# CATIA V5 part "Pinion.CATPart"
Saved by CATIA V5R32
Part number: Part3
Bounding box of the stored display mesh (mm): x -50 to 70, y -20 to 20, z -20 to 20
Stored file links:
  D:\PROJECTS\Project 2022\CATIA V5 6R 2022\Resources\Part Files\c16_catia_v5_6r2022_prt\Rack Joint(Fig16-57)\Pinion.CATPart
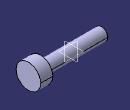
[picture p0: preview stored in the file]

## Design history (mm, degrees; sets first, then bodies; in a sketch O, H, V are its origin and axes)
Body1 (main body)
  Sketch1 on yz-plane, origin (0, 0, 0), H (0, 1, 0), V (0, 0, 1)
    reference intersected line E1 through (0, 0) direction (-1, 0) from xy-plane
    reference intersected line E3 through (0, 0) direction (0, 1) from zx-plane
    reference intersected line E4 through (0, 0) direction (-1, 0) from xy-plane
    reference intersected line E6 through (0, 0) direction (0, 1) from zx-plane
    reference intersected line E7 through (0, 0) direction (-1, 0) from xy-plane
    reference intersected line E9 through (0, 0) direction (0, 1) from zx-plane
    circle A1 centre (0, 0) radius 10
    radius A1 = 10
    vertical: E3 V, E6 V, E9 V
    horizontal: E1 H, E4 H, E7 H
  Pad1: profile Sketch1, direction (1, 0, 0), length 50, mirrored extent
  Sketch2 on end face of Pad1, origin (50, 0, 0), H (0, 1, 0), V (0, 0, 1)
    circle A1 centre (0, 0) radius 20
    radius A1 = 20
  Pad2: profile Sketch2, direction (1, 0, 0), length 20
